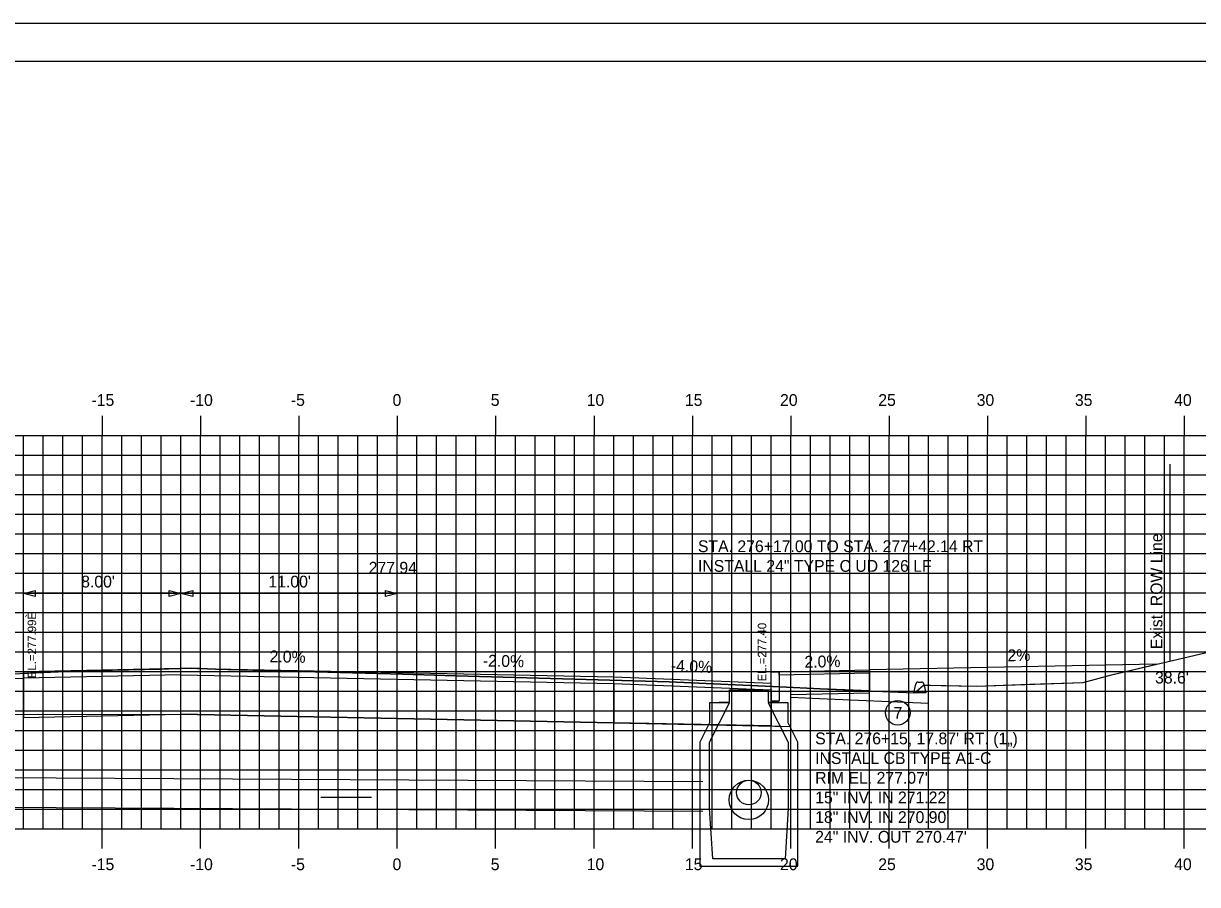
# Model space of a CAD drawing. Extents: x 853785 to 853955, y 366268 to 366378.
# Drawn here: x 853849.4 to 853909.1, y 366334.4 to 366378.2 of the extents above; entities that cross this region are included whole.
import ezdxf

# ---------------------------------------------------------------- set-up
doc = ezdxf.new("R2010")
doc.units = 0
for name, color, linetype in [('ANNOTATION', 7, 'Continuous'), ('BORDER', 7, 'Continuous'), ('D_Curb_Type_1_Rt', 7, 'Continuous'), ('D_Drainage_CB_TypeA1-B1', 7, 'Continuous'), ('D_Drainage_Culvert', 7, 'Continuous'), ('D_Drainage_Text', 7, 'Continuous'), ('D_Roadway_Centerline_Text', 7, 'Continuous'), ('D_Roadway_Edge_Shoulder', 7, 'Continuous'), ('D_Roadway_FinishedGrade', 7, 'Continuous'), ('D_Roadway_Sidewalks_Paved', 7, 'Continuous'), ('D_Roadway_SubGrade', 7, 'Continuous'), ('D_Text_Standard', 7, 'Continuous'), ('DIMENSIONS', 7, 'Continuous'), ('E_ROW_Line', 7, 'Continuous'), ('H_V ANNOTATION', 7, 'Continuous'), ('JUNK COM EXC', 7, 'Continuous'), ('JUNK FILL', 7, 'Continuous'), ('MAJOR', 7, 'Continuous'), ('MINOR', 7, 'Continuous'), ('PDRAIN', 7, 'Continuous'), ('PLOT BOUNDARY', 7, 'Continuous'), ('S_Curb_Type_3', 7, 'Continuous'), ('S_Roadway_Centerline', 7, 'Continuous')]:
    doc.layers.add(name, color=color, linetype=linetype)

msp = doc.modelspace()

# ---------------------------------------------------------------- linework, layer by layer
at = {"layer": 'ANNOTATION'}
msp.add_line((853864.542, 366338.843), (853867.128, 366338.843), dxfattribs=at)
at = {"layer": 'BORDER'}
msp.add_line((853953.435, 366376.236), (853793.435, 366376.236), dxfattribs=at)
at = {"layer": 'D_Curb_Type_1_Rt'}
msp.add_lwpolyline([(853887.853, 366345.222), (853887.853, 366343.722), (853887.436, 366343.722), (853887.436, 366345.222)], close=True, dxfattribs=at)
at = {"layer": 'D_Drainage_CB_TypeA1-B1'}
for p, q in [((853884.304, 366343.641), (853884.304, 366342.624)), ((853884.304, 366341.64), (853885.321, 366343.641)), ((853885.321, 366343.641), (853884.304, 366343.641)), ((853888.307, 366343.641), (853887.29, 366343.641)), ((853887.29, 366343.641), (853888.307, 366341.64)), ((853888.307, 366342.624), (853888.307, 366343.641)), ((853884.304, 366342.624), (853883.812, 366341.64)), ((853888.799, 366341.64), (853888.307, 366342.624)), ((853883.812, 366341.64), (853883.812, 366335.346)), ((853884.304, 366338.294), (853884.304, 366341.64)), ((853888.307, 366341.64), (853888.307, 366338.294)), ((853888.799, 366335.346), (853888.799, 366341.64)), ((853884.468, 366335.706), (853884.304, 366338.294)), ((853888.307, 366338.294), (853888.143, 366335.706)), ((853883.812, 366335.346), (853888.799, 366335.346)), ((853888.143, 366335.706), (853884.468, 366335.706))]:
    msp.add_line(p, q, dxfattribs=at)
msp.add_lwpolyline([(853884.796, 366343.683), (853885.321, 366343.683), (853885.321, 366344.306), (853887.29, 366344.306), (853887.29, 366343.683), (853887.814, 366343.683)], dxfattribs=at)
at = {"layer": 'D_Drainage_Culvert'}
for p, q in [((853846.709, 366339.851), (853883.967, 366339.636)), ((853846.709, 366338.351), (853883.958, 366338.136))]:
    msp.add_line(p, q, dxfattribs=at)
msp.add_circle((853886.305, 366339.081), 0.625, dxfattribs=at)
at = {"layer": 'D_Drainage_Text'}
msp.add_circle((853893.874, 366343.138), 0.625, dxfattribs=at)
at = {"layer": 'D_Roadway_Edge_Shoulder'}
msp.add_line((853849.435, 366345.228), (853849.435, 366344.896), dxfattribs=at)
for points in [[(853849.435, 366345.228), (853857.435, 366345.398), (853879.435, 366344.958), (853887.436, 366344.638)], [(853834.931, 366344.965), (853837.645, 366345.011), (853840.458, 366345.065), (853840.894, 366345.073), (853841.32, 366345.082), (853845.594, 366345.148), (853847.367, 366345.186), (853848.927, 366345.219), (853849.435, 366345.228)], [(853834.931, 366344.632), (853837.651, 366344.678), (853840.465, 366344.732), (853840.901, 366344.74), (853841.326, 366344.749), (853845.6, 366344.815), (853849.435, 366344.896)]]:
    msp.add_lwpolyline(points, dxfattribs=at)
at = {"layer": 'D_Roadway_FinishedGrade'}
msp.add_line((853907.031, 366345.606), (853892.441, 366345.313), dxfattribs=at)
at = {"layer": 'D_Roadway_Sidewalks_Paved'}
msp.add_lwpolyline([(853887.853, 366345.222), (853892.441, 366345.313), (853892.441, 366345.147), (853887.853, 366345.055)], close=True, dxfattribs=at)
at = {"layer": 'D_Roadway_SubGrade'}
for p, q in [((853857.439, 366345.065), (853849.435, 366344.896)), ((853849.435, 366344.896), (853849.435, 366343.056)), ((853857.439, 366343.065), (853857.439, 366345.065)), ((853895.435, 366343.621), (853895.435, 366344.542)), ((853833.931, 366343.3), (853849.435, 366343.056)), ((853849.435, 366343.056), (853857.439, 366343.065))]:
    msp.add_line(p, q, dxfattribs=at)
for points in [[(853857.435, 366343.065), (853857.435, 366345.065), (853868.435, 366344.845), (853879.435, 366344.625), (853879.435, 366342.625), (853868.435, 366342.845)], [(853879.436, 366344.625), (853887.436, 366344.305), (853887.436, 366342.465), (853879.436, 366342.625)]]:
    msp.add_lwpolyline(points, close=True, dxfattribs=at)
for points in [[(853887.44, 366342.466), (853888.44, 366342.446), (853888.44, 366344.067), (853892.442, 366344.147), (853892.442, 366345.147)], [(853888.44, 366343.928), (853889.902, 366343.858), (853895.435, 366343.621)]]:
    msp.add_lwpolyline(points, dxfattribs=at)
at = {"layer": 'DIMENSIONS'}
for p, q in [((853849.435, 366345.242), (853849.435, 366349.606)), ((853857.435, 366345.562), (853857.435, 366349.606)), ((853868.435, 366345.378), (853868.435, 366349.606)), ((853857.435, 366349.206), (853849.435, 366349.206)), ((853868.435, 366349.206), (853857.435, 366349.206))]:
    msp.add_line(p, q, dxfattribs=at)
for points in [[(853850.035, 366349.056), (853849.435, 366349.206), (853850.035, 366349.356)], [(853856.835, 366349.356), (853857.435, 366349.206), (853856.835, 366349.056)], [(853858.035, 366349.056), (853857.435, 366349.206), (853858.035, 366349.356)], [(853867.835, 366349.356), (853868.435, 366349.206), (853867.835, 366349.056)]]:
    msp.add_lwpolyline(points, close=True, dxfattribs=at)
at = {"layer": 'E_ROW_Line'}
msp.add_line((853907.722, 366345.77), (853907.722, 366355.77), dxfattribs=at)
at = {"layer": 'JUNK COM EXC'}
msp.add_lwpolyline([(853849.437, 366345.137), (853849.439, 366342.905), (853857.439, 366343.065), (853879.435, 366342.625), (853888.44, 366342.446), (853888.44, 366344.067), (853892.442, 366344.147), (853892.442, 366344.25), (853889.924, 366344.358), (853887.88, 366344.455), (853882.25, 366344.718), (853871.405, 366345.017), (853868.696, 366345.096), (853859.192, 366345.36), (853857.996, 366345.398), (853856.827, 366345.374), (853856.686, 366345.371), (853856.588, 366345.368), (853856.399, 366345.361), (853852.331, 366345.267), (853851.596, 366345.229), (853849.437, 366345.137)], dxfattribs=at)
at = {"layer": 'JUNK FILL'}
msp.add_lwpolyline([(853892.442, 366344.25), (853894.683, 366344.154), (853894.82, 366344.238), (853895.189, 366344.548), (853895.533, 366344.54), (853897.88, 366344.491), (853900.588, 366344.587), (853903.297, 366344.684), (853904.739, 366345.062), (853907.031, 366345.606), (853892.441, 366345.313), (853892.435, 366345.313), (853892.435, 366345.147), (853892.442, 366345.147)], close=True, dxfattribs=at)
at = {"layer": 'MAJOR'}
for p, q in [((853853.435, 366358.238), (853853.435, 366357.236)), ((853858.435, 366358.238), (853858.435, 366357.236)), ((853863.435, 366358.238), (853863.435, 366357.236)), ((853868.435, 366358.238), (853868.435, 366357.236)), ((853873.435, 366358.238), (853873.435, 366357.236)), ((853878.435, 366358.238), (853878.435, 366357.236)), ((853883.435, 366358.238), (853883.435, 366357.236)), ((853888.435, 366358.238), (853888.435, 366357.236)), ((853893.435, 366358.238), (853893.435, 366357.236)), ((853898.435, 366358.238), (853898.435, 366357.236)), ((853903.435, 366358.238), (853903.435, 366357.236)), ((853908.435, 366358.238), (853908.435, 366357.236)), ((853798.435, 366357.236), (853938.435, 366357.236)), ((853798.435, 366357.236), (853938.435, 366357.236)), ((853853.435, 366337.236), (853853.435, 366357.236)), ((853858.435, 366337.236), (853858.435, 366357.236)), ((853863.435, 366337.236), (853863.435, 366357.236)), ((853868.435, 366337.236), (853868.435, 366357.236)), ((853873.435, 366337.236), (853873.435, 366357.236)), ((853878.435, 366337.236), (853878.435, 366357.236)), ((853883.435, 366337.236), (853883.435, 366357.236)), ((853888.435, 366337.236), (853888.435, 366357.236)), ((853893.435, 366337.236), (853893.435, 366357.236)), ((853898.435, 366337.236), (853898.435, 366357.236)), ((853903.435, 366337.236), (853903.435, 366357.236)), ((853908.435, 366337.236), (853908.435, 366357.236)), ((853798.435, 366352.236), (853938.435, 366352.236)), ((853798.435, 366347.236), (853938.435, 366347.236)), ((853798.435, 366342.236), (853938.435, 366342.236)), ((853798.435, 366337.236), (853938.435, 366337.236)), ((853798.435, 366337.236), (853938.435, 366337.236)), ((853853.435, 366336.234), (853853.435, 366337.236)), ((853858.435, 366336.234), (853858.435, 366337.236)), ((853863.435, 366336.234), (853863.435, 366337.236)), ((853868.435, 366336.234), (853868.435, 366337.236)), ((853873.435, 366336.234), (853873.435, 366337.236)), ((853878.435, 366336.234), (853878.435, 366337.236)), ((853883.435, 366336.234), (853883.435, 366337.236)), ((853888.435, 366336.234), (853888.435, 366337.236)), ((853893.435, 366336.234), (853893.435, 366337.236)), ((853898.435, 366336.234), (853898.435, 366337.236)), ((853903.435, 366336.234), (853903.435, 366337.236)), ((853908.435, 366336.234), (853908.435, 366337.236))]:
    msp.add_line(p, q, dxfattribs=at)
at = {"layer": 'MINOR'}
for p, q in [((853849.435, 366337.236), (853849.435, 366357.236)), ((853850.435, 366337.236), (853850.435, 366357.236)), ((853851.435, 366337.236), (853851.435, 366357.236)), ((853852.435, 366337.236), (853852.435, 366357.236)), ((853854.435, 366337.236), (853854.435, 366357.236)), ((853855.435, 366337.236), (853855.435, 366357.236)), ((853856.435, 366337.236), (853856.435, 366357.236)), ((853857.435, 366337.236), (853857.435, 366357.236)), ((853859.435, 366337.236), (853859.435, 366357.236)), ((853860.435, 366337.236), (853860.435, 366357.236)), ((853861.435, 366337.236), (853861.435, 366357.236)), ((853862.435, 366337.236), (853862.435, 366357.236)), ((853864.435, 366337.236), (853864.435, 366357.236)), ((853865.435, 366337.236), (853865.435, 366357.236)), ((853866.435, 366337.236), (853866.435, 366357.236)), ((853867.435, 366337.236), (853867.435, 366357.236)), ((853869.435, 366337.236), (853869.435, 366357.236)), ((853870.435, 366337.236), (853870.435, 366357.236)), ((853871.435, 366337.236), (853871.435, 366357.236)), ((853872.435, 366337.236), (853872.435, 366357.236)), ((853874.435, 366337.236), (853874.435, 366357.236)), ((853875.435, 366337.236), (853875.435, 366357.236)), ((853876.435, 366337.236), (853876.435, 366357.236)), ((853877.435, 366337.236), (853877.435, 366357.236)), ((853879.435, 366337.236), (853879.435, 366357.236)), ((853880.435, 366337.236), (853880.435, 366357.236)), ((853881.435, 366337.236), (853881.435, 366357.236)), ((853882.435, 366337.236), (853882.435, 366357.236)), ((853884.435, 366337.236), (853884.435, 366357.236)), ((853885.435, 366337.236), (853885.435, 366357.236)), ((853886.435, 366337.236), (853886.435, 366357.236)), ((853887.435, 366337.236), (853887.435, 366357.236)), ((853889.435, 366337.236), (853889.435, 366357.236)), ((853890.435, 366337.236), (853890.435, 366357.236)), ((853891.435, 366337.236), (853891.435, 366357.236)), ((853892.435, 366337.236), (853892.435, 366357.236)), ((853894.435, 366337.236), (853894.435, 366357.236)), ((853895.435, 366337.236), (853895.435, 366357.236)), ((853896.435, 366337.236), (853896.435, 366357.236)), ((853897.435, 366337.236), (853897.435, 366357.236)), ((853899.435, 366337.236), (853899.435, 366357.236)), ((853900.435, 366337.236), (853900.435, 366357.236)), ((853901.435, 366337.236), (853901.435, 366357.236)), ((853902.435, 366337.236), (853902.435, 366357.236)), ((853904.435, 366337.236), (853904.435, 366357.236)), ((853905.435, 366337.236), (853905.435, 366357.236)), ((853906.435, 366337.236), (853906.435, 366357.236)), ((853907.435, 366337.236), (853907.435, 366357.236)), ((853798.435, 366356.236), (853938.435, 366356.236)), ((853798.435, 366355.236), (853938.435, 366355.236)), ((853798.435, 366354.236), (853938.435, 366354.236)), ((853798.435, 366353.236), (853938.435, 366353.236)), ((853798.435, 366351.236), (853938.435, 366351.236)), ((853798.435, 366350.236), (853938.435, 366350.236)), ((853798.435, 366349.236), (853938.435, 366349.236)), ((853798.435, 366348.236), (853938.435, 366348.236)), ((853798.435, 366346.236), (853938.435, 366346.236)), ((853798.435, 366345.236), (853938.435, 366345.236)), ((853798.435, 366344.236), (853938.435, 366344.236)), ((853798.435, 366343.236), (853938.435, 366343.236)), ((853798.435, 366341.236), (853938.435, 366341.236)), ((853798.435, 366340.236), (853938.435, 366340.236)), ((853798.435, 366339.236), (853938.435, 366339.236)), ((853798.435, 366338.236), (853938.435, 366338.236))]:
    msp.add_line(p, q, dxfattribs=at)
at = {"layer": 'PDRAIN'}
msp.add_circle((853886.305, 366338.706), 1, dxfattribs=at)
at = {"layer": 'PLOT BOUNDARY'}
msp.add_lwpolyline([(853785.342, 366268.177), (853955.342, 366268.177), (853955.342, 366378.177), (853785.342, 366378.177)], close=True, dxfattribs=at)
at = {"layer": 'S_Curb_Type_3'}
for points in [[(853895.205, 366344.599), (853895.308, 366344.154), (853894.683, 366344.154), (853894.785, 366344.599)], [(853894.907, 366344.696), (853895.083, 366344.696)]]:
    msp.add_lwpolyline(points, dxfattribs=at)
for centre, start, end in [((853894.907, 366344.571), 90, 167.00538), ((853895.083, 366344.571), 12.99462, 90)]:
    msp.add_arc(centre, 0.125, start, end, dxfattribs=at)
at = {"layer": 'S_Roadway_Centerline'}
msp.add_lwpolyline([(853841.417, 366344.797), (853851.596, 366345.229), (853852.331, 366345.267), (853856.399, 366345.361), (853856.588, 366345.368), (853856.686, 366345.371), (853856.827, 366345.374), (853857.996, 366345.398), (853859.192, 366345.36), (853868.696, 366345.096), (853871.405, 366345.017), (853882.25, 366344.718), (853887.88, 366344.455), (853889.924, 366344.358), (853894.683, 366344.154), (853894.82, 366344.238), (853895.189, 366344.548), (853897.88, 366344.491), (853903.297, 366344.684), (853904.739, 366345.062), (853909.779, 366346.258)], dxfattribs=at)

# ---------------------------------------------------------------- texts
at = {"layer": 'ANNOTATION'}
for s, rotation, p in [('2.0%', 358.85423, (853861.941, 366345.709)), ('-2.0%', 358.85424, (853872.778, 366345.492)), ('2.0%', 1.14566, (853889.136, 366345.426)), ('2%', 1.14841, (853899.457, 366345.754)), ('-4.0%', 357.70939, (853882.332, 366345.243))]:
    msp.add_text(s, height=0.6, rotation=rotation, dxfattribs=at).set_placement(p)
at = {"layer": 'D_Drainage_Text'}
for s, p in [('STA. 276+17.00 TO STA. 277+42.14 RT', (853883.716, 366351.303)), ('INSTALL 24" TYPE C UD 126 LF', (853883.716, 366350.303)), ("STA. 276+15, 17.87' RT. (1„)", (853889.675, 366341.532)), ('INSTALL CB TYPE A1-C', (853889.675, 366340.532)), ("RIM EL. 277.07'", (853889.675, 366339.532)), ('15" INV. IN 271.22\'', (853889.675, 366338.532)), ('18" INV. IN 270.90\'', (853889.675, 366337.532)), ('24" INV. OUT 270.47\'', (853889.675, 366336.532))]:
    msp.add_text(s, height=0.6, dxfattribs=at).set_placement(p)
at = {"layer": 'D_Roadway_Centerline_Text'}
msp.add_text('277.94', height=0.6, dxfattribs=at).set_placement((853866.98, 366350.21))
at = {"layer": 'D_Text_Standard'}
for s, p in [(' EL.=277.99È', (853850.079, 366344.733)), (' EL.=277.40', (853887.19, 366344.569))]:
    msp.add_text(s, height=0.4335, rotation=90, dxfattribs=at).set_placement(p)
msp.add_text("38.6'", height=0.6, dxfattribs=at).set_placement((853906.951, 366344.625))
at = {"layer": 'DIMENSIONS'}
for s, p in [("8.00'", (853852.368, 366349.506)), ("11.00'", (853861.884, 366349.506))]:
    msp.add_text(s, height=0.6, dxfattribs=at).set_placement(p)
at = {"layer": 'E_ROW_Line'}
msp.add_text('Exist. ROW Line', height=0.6, rotation=90, dxfattribs=at).set_placement((853907.322, 366346.37))
at = {"layer": 'H_V ANNOTATION'}
for s, p in [('-15', (853852.892, 366358.736)), ('-10', (853857.9, 366358.736)), ('-5', (853863.026, 366358.736)), ('0', (853868.194, 366358.736)), ('5', (853873.186, 366358.736)), ('10', (853878.061, 366358.736)), ('15', (853883.053, 366358.736)), ('20', (853887.889, 366358.736)), ('25', (853892.881, 366358.736)), ('30', (853897.884, 366358.736)), ('35', (853902.876, 366358.736)), ('40', (853907.921, 366358.736)), ('7', (853893.66, 366342.834)), ('-15', (853852.892, 366335.136)), ('-10', (853857.9, 366335.136)), ('-5', (853863.026, 366335.136)), ('0', (853868.194, 366335.136)), ('5', (853873.186, 366335.136)), ('10', (853878.061, 366335.136)), ('15', (853883.053, 366335.136)), ('20', (853887.889, 366335.136)), ('25', (853892.881, 366335.136)), ('30', (853897.884, 366335.136)), ('35', (853902.876, 366335.136)), ('40', (853907.921, 366335.136))]:
    msp.add_text(s, height=0.6, dxfattribs=at).set_placement(p)
at = {"layer": 'S_Roadway_Centerline'}
for s, p in [('C', (853868.691, 366345.096)), ('L', (853868.696, 366345.089))]:
    msp.add_text(s, height=0.0146, dxfattribs=at).set_placement(p)

doc.saveas('drawing.dxf')
